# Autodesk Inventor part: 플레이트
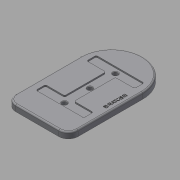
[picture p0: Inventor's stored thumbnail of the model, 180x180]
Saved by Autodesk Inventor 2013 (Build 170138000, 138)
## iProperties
Created: 2016-08
Part Number: 플레이트
Material: 일반
Document SubType Name: Modeling
Designer: mduedu
Density: 2.71 g/cm^3
Author: mduedu
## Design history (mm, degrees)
sketch "스케치1" dims "d0" = 220, "d2" = 130
  geometry: L1 (110, 65)-(-45, 65); L2 (-45, 65)-(-45, -65); L3 (-45, -65)-(110, -65); L4 (45, -65)-(45, 65); L5 (45, 65)-(-45, -65); L6 (-45, 65)-(45, -65); L7 (110, -65)-(110, 65); 5 further points
  constraints: 14 end point, 5 midpoint, 3 parallel, 2 point on line, 2 vertical alignment, 1 coincident, 1 horizontal, 1 perpendicular, 1 vertical, 4 other
extrude "돌출1" new body sketch "스케치1" distance "d3" = 13; taper "d4" = 0 deg
sketch "스케치2"
  geometry: L1 (-63, -50)-(63, -50); L2 (63, -50)-(63, 50); L3 (63, 50)-(-63, 50); L4 (-63, 50)-(-63, -50); L5 (-63, -50)-(63, 50); L6 (63, -50)-(-63, 50); L7 (-63, 50)-(-43, 50); L8 (-43, 50)-(-43, -50); L9 (-43, -50)-(-63, -50); L10 (-63, -50)-(-63, 50); L11 (63, 50)-(43, 50); L12 (43, 50)-(43, -50); L13 (43, -50)-(63, -50); L14 (63, -50)-(63, 50); L15 (-43, -10)-(43, -10); L16 (43, -10)-(43, 10); L17 (43, 10)-(-43, 10); L18 (-43, 10)-(-43, -10); L19 (-43, -10)-(43, 10); L20 (43, -10)-(-43, 10); 1 further point
  constraints: 40 end point, 8 parallel, 4 horizontal, 4 midpoint, 4 perpendicular, 3 point on line
  dimensions: "d18" = 126 distance of L3.end L2.end; "d19" = 100 distance of L2.end L1.end; "d20" = 20 distance of L8.end L9.end; "d21" = 20 distance of L12.end L13.end (= d20); "d22" = 20 distance of L15.end L16.end
extrude "돌출3" cut sketch "스케치2" distance "d23" = 3; taper "d24" = 0 deg
fillet "모깎기6" dims "d25" = 3
sketch "스케치4"
  geometry: L1 (-40, -10)-(40, -10) reference; L2 (43, -13)-(43, -47) reference; L3 (40, 10)-(-40, 10) reference; L4 (-43, 13)-(-43, 47) reference; L5 (45, -65)-(-110, -65) reference; L6 (-110, 65)-(45, 65) reference; L7 (-53, 40)-(-53, -40); L8 (53, 40)-(53, -40); L9 (-53, 0)-(53, 0); L10 (-46, 50)-(-60, 50) reference; L11 (-63, 47)-(-63, -47) reference; L12 (-60, -50)-(-46, -50) reference; L13 (-43, -47)-(-43, -13) reference; L14 (46, -50)-(60, -50) reference; L15 (63, -47)-(63, 47) reference; L16 (60, 50)-(46, 50) reference; L17 (43, 47)-(43, 13) reference; L18 (-110, -65)-(-110, 65) reference; C1 r 5 at (-53, 0); C2 r 5 at (0, 0); C3 r 5 at (53, 0); A1 r 3 centre (-40, -13) between (-40, -10) and (-43, -13) reference; A2 r 3 centre (40, -13) between (43, -13) and (40, -10) reference; A3 r 3 centre (40, 13) between (40, 10) and (43, 13) reference; A4 r 3 centre (-40, 13) between (-43, 13) and (-40, 10) reference; A5 r 65 centre (45, 0) between (45, -65) and (45, 65) reference; A6 r 3 centre (-46, 47) between (-43, 47) and (-46, 50) reference; A7 r 3 centre (-60, 47) between (-60, 50) and (-63, 47) reference; A8 r 3 centre (-60, -47) between (-63, -47) and (-60, -50) reference; A9 r 3 centre (-46, -47) between (-46, -50) and (-43, -47) reference; A10 r 3 centre (46, -47) between (43, -47) and (46, -50) reference; A11 r 3 centre (60, -47) between (60, -50) and (63, -47) reference; A12 r 3 centre (60, 47) between (63, 47) and (60, 50) reference; A13 r 3 centre (46, 47) between (46, 50) and (43, 47) reference; 1 further point
  constraints: 6 end point, 3 centre point, 3 coincident, 2 midpoint, 1 parallel, 1 perpendicular
  dimensions: "d26" = 10 diameter of C1; "d27" = 10 diameter of C2; "d28" = 10 diameter of C3
extrude "돌출4" cut sketch "스케치4" stored distance "d29" = 3; taper "d30" = 0 deg
chamfer "모따기2" distance "d31" = 1; stored, may be unused: second distance "d32" = 2, angle "d33" = 45 deg
fillet "모깎기7" dims "d34" = 20
fillet "모깎기1" dims "d14" = 3
sketch "스케치3"
  geometry: L1 (-90, -65)-(45, -65) reference; 3 further points
  constraints: 1 vertical alignment, 1 other
  dimensions: "d15" = 12 distance from line of point (0, -53) L1
feature "엠보싱1" sketch "스케치3" dims "d16" = 0.5, "d17" = 0
node "솔리드1"
node "절단 모서리 투영1"
